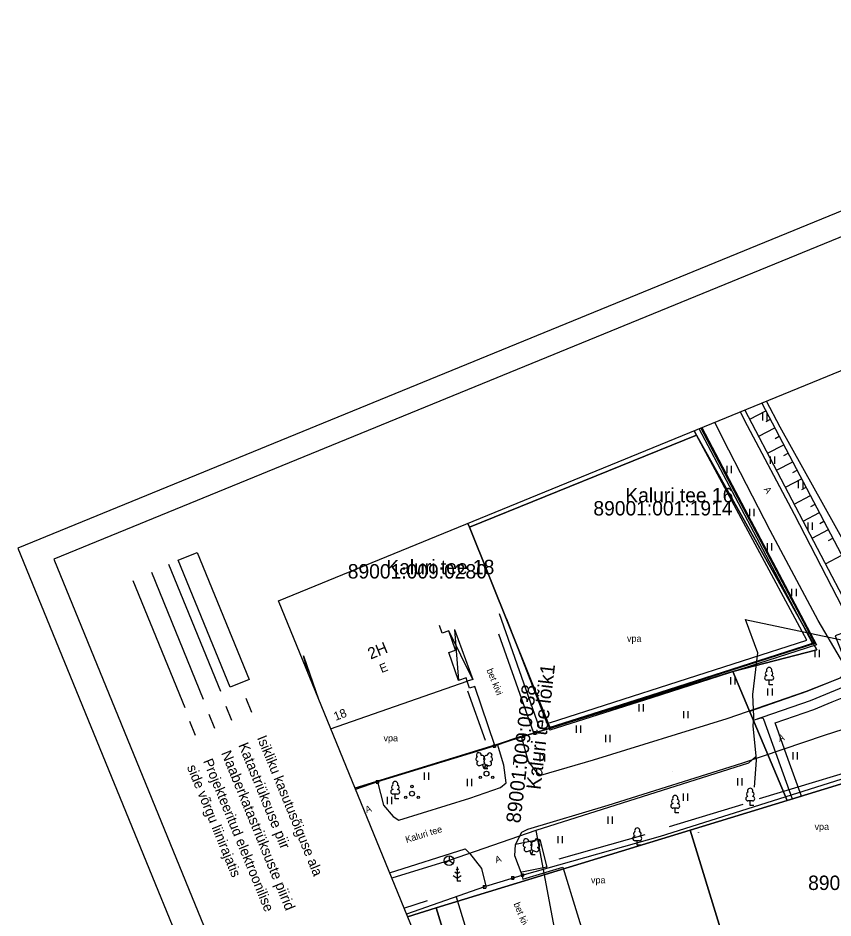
# Model space of a CAD drawing. Extents: x -52238384 to 549205, y 6582846 to 57187752.
# Drawn here: x 546435.6 to 546520.5, y 6597179.7 to 6597273.4 of the extents above; entities that cross this region are included whole.
import ezdxf

# ---------------------------------------------------------------- set-up
doc = ezdxf.new("R2010")
doc.units = 0
for name, color, linetype in [('kaluri tee mõõdistus$0$AED', 7, 'Continuous'), ('kaluri tee mõõdistus$0$HALJASTUS', 7, 'Continuous'), ('kaluri tee mõõdistus$0$HOONE', 7, 'Continuous'), ('kaluri tee mõõdistus$0$HOONEDET', 7, 'Continuous'), ('kaluri tee mõõdistus$0$PUU', 7, 'Continuous'), ('kaluri tee mõõdistus$0$Reljeef', 7, 'Continuous'), ('kaluri tee mõõdistus$0$SIKAEV', 7, 'Continuous'), ('kaluri tee mõõdistus$0$SITRASS', 7, 'Continuous'), ('kaluri tee mõõdistus$0$TEE', 7, 'Continuous'), ('KANAL_ELEMENDID', 7, 'Continuous'), ('KANAL_KAEVUD', 7, 'Continuous'), ('Kasutusala', 7, 'Continuous'), ('L_AADRESS', 7, 'Continuous'), ('Level 52', 7, 'Continuous'), ('Level 63', 7, 'Continuous'), ('PIIR', 7, 'Continuous'), ('TUNNUS', 7, 'Continuous')]:
    doc.layers.add(name, color=color, linetype=linetype)

# ---------------------------------------------------------------- blocks, each defined once
blk = doc.blocks.new('kaluri tee mõõdistus$0$HEIN')
at = {"layer": 'kaluri tee mõõdistus$0$HALJASTUS'}
for p, q in [((-46, 76), (-46, -76)), ((46, 76), (46, -76))]:
    blk.add_line(p, q, dxfattribs=at)
blk = doc.blocks.new('kaluri tee mõõdistus$0$MAND1')
at = {"layer": 'kaluri tee mõõdistus$0$PUU'}
for p, q in [((0, 230), (-25, 247)), ((0, 300), (0, 0)), ((25, 247), (0, 230)), ((-85, 118), (0, 61)), ((0, 150), (-53, 186)), ((53, 186), (0, 150)), ((0, 61), (85, 118)), ((72, 0), (0, 0))]:
    blk.add_line(p, q, dxfattribs=at)
blk = doc.blocks.new('kaluri tee mõõdistus$0$LEHTP1')
at = {"layer": 'kaluri tee mõõdistus$0$PUU'}
for p, q in [((48, 95), (-48, 95)), ((0, 0), (0, 95)), ((76, 0), (0, 0))]:
    blk.add_line(p, q, dxfattribs=at)
for centre, radius, start, end in [((-47, 142), 47.5, 90.0016, 269.3953), ((-34, 235), 46.5, 109.0217, 253.1415), ((0, 304), 55.4, 332.5799, 207.4201), ((34, 235), 46.5, 286.8508, 70.9859), ((47, 142), 47.5, 270.6047, 89.9984)]:
    blk.add_arc(centre, radius, start, end, dxfattribs=at)
blk = doc.blocks.new('kaluri tee mõõdistus$0$LEHTP2')
at = {"layer": 'kaluri tee mõõdistus$0$PUU'}
for p, q in [((-88, 67), (1, 102)), ((0, 0), (-35, 88)), ((0, 0), (36, 88)), ((76, 0), (0, 0)), ((1, 102), (89, 66))]:
    blk.add_line(p, q, dxfattribs=at)
blk.add_lwpolyline([(1, 201), (-3, 186), (-3, 182), (-1, 176), (3, 169), (4, 165), (1, 158), (-4, 148), (-5, 143), (-4, 140), (-2, 134), (5, 122), (6, 118), (5, 114), (2, 107), (1, 102)], dxfattribs=at)
for centre, radius, start, end in [((-126, 201), 44.8, 111.4304, 274.4987), ((-111, 283), 51.2, 111.5027, 232.5173), ((-111, 283), 51.2, 350.4856, 111.5002), ((-44, 233), 44.8, 308.5041, 111.5725), ((1, 153), 47.5, 66.7655, 111.5015), ((48, 232), 45, 67.7016, 230.5126), ((116, 281), 51.2, 67.6168, 188.6314), ((129, 199), 44.8, 264.6183, 67.6866), ((116, 281), 51.2, 306.5997, 67.6143), ((-105, 112), 47.5, 111.5014, 291.5004), ((107, 110), 47.5, 247.6166, 67.6155)]:
    blk.add_arc(centre, radius, start, end, dxfattribs=at)
blk = doc.blocks.new('kaluri tee mõõdistus$0$VARPOS')
at = {"layer": 'kaluri tee mõõdistus$0$AED'}
for p, q in [((-25, 25), (-25, -25)), ((-25, 25), (25, 25)), ((25, 25), (25, -25)), ((-25, -25), (25, -25))]:
    blk.add_line(p, q, dxfattribs=at)
blk = doc.blocks.new('kaluri tee mõõdistus$0$PQQSAS')
at = {"layer": 'kaluri tee mõõdistus$0$PUU'}
for centre, radius in [((0, 0), 50), ((0, 150), 25), ((-130, -75), 25), ((130, -75), 25)]:
    blk.add_circle(centre, radius, dxfattribs=at)
blk = doc.blocks.new('kaluri tee mõõdistus$0$SIKAEV')
at = {"layer": 'kaluri tee mõõdistus$0$SIKAEV'}
for p, q in [((0, 0), (-83, -55)), ((0, 100), (0, 0)), ((0, 0), (83, -55))]:
    blk.add_line(p, q, dxfattribs=at)
blk.add_circle((0, 0), 100, dxfattribs=at)
blk = doc.blocks.new('VKT_kk_olemas_w')
at = {"layer": 'KANAL_ELEMENDID'}
blk.add_line((0, 0), (0, 0), dxfattribs=at)
blk.add_circle((0, 0), 0.1, dxfattribs=at)

msp = doc.modelspace()

# ---------------------------------------------------------------- linework, layer by layer
at = {"layer": 'kaluri tee mõõdistus$0$AED'}
for points in [[(546506.844, 6597230.752), (546509.707, 6597225.356), (546518.818, 6597208.138), (546501.644, 6597202.59), (546491.016, 6597199.217), (546490.926, 6597199.503), (546501.553, 6597202.876), (546517.54, 6597208.004), (546518.391, 6597208.305), (546512.913, 6597218.694), (546506.569, 6597230.64)], [(546506.732, 6597230.706), (546513.987, 6597217.039), (546518.619, 6597208.25), (546491.076, 6597199.407)], [(546490.926, 6597199.503), (546490.866, 6597199.572), (546486.525, 6597210.804)], [(546491.076, 6597199.407), (546489.432, 6597198.954)], [(546488.252, 6597198.617), (546485.218, 6597197.583)], [(546489.432, 6597198.954), (546488.252, 6597198.617)], [(546485.218, 6597197.583), (546473.034, 6597193.848)], [(546488.135, 6597184.138), (546502.555, 6597188.204), (546524.017, 6597194.973)], [(546473.034, 6597193.848), (546470.74, 6597193.068)], [(546489.963, 6597187.858), (546490.701, 6597184.976), (546488.077, 6597184.441)], [(546484.2, 6597182.912), (546476.056, 6597180.077)]]:
    msp.add_lwpolyline(points, dxfattribs=at)
at = {"layer": 'kaluri tee mõõdistus$0$HALJASTUS'}
for p, q in [((546484.29, 6597198.152), (546482.473, 6597203.283)), ((546491.999, 6597185.827), (546500.964, 6597188.363))]:
    msp.add_line(p, q, dxfattribs=at)
for points in [[(546490.976, 6597199.992), (546517.792, 6597208.595), (546506.071, 6597230.436)], [(546489.945, 6597199.476), (546485.749, 6597211.343)], [(546526.412, 6597196.164), (546512.843, 6597192.092)], [(546511.143, 6597191.484), (546503.443, 6597189.176)], [(546489.963, 6597187.858), (546487.425, 6597187.304)], [(546475.807, 6597180.686), (546478.247, 6597181.491)]]:
    msp.add_lwpolyline(points, dxfattribs=at)
at = {"layer": 'kaluri tee mõõdistus$0$HOONE'}
for p, q in [((546481.087, 6597209.717), (546482.969, 6597204.513)), ((546482.969, 6597204.513), (546482.397, 6597204.333))]:
    msp.add_line(p, q, dxfattribs=at)
for points in [[(546468.163, 6597199.366), (546482.397, 6597204.333), (546482.287, 6597204.669), (546481.497, 6597204.394), (546480.479, 6597207.33), (546481.174, 6597207.577), (546480.475, 6597209.588), (546479.789, 6597209.34), (546479.503, 6597210.147)], [(546465.322, 6597206.98), (546466.892, 6597202.471)]]:
    msp.add_lwpolyline(points, dxfattribs=at)
at = {"layer": 'kaluri tee mõõdistus$0$HOONEDET'}
for p, q in [((546482.969, 6597204.513), (546480.475, 6597209.588)), ((546481.087, 6597209.717), (546481.497, 6597204.394)), ((546465.842, 6597205.039), (546465.322, 6597206.98))]:
    msp.add_line(p, q, dxfattribs=at)
at = {"layer": 'kaluri tee mõõdistus$0$Reljeef'}
for p, q in [((546523.368, 6597209.639), (546511.346, 6597232.595)), ((546511.851, 6597231.631), (546513.532, 6597232.515)), ((546513.555, 6597231.397), (546513.997, 6597231.63)), ((546512.779, 6597229.859), (546514.463, 6597230.745)), ((546514.486, 6597229.627), (546514.928, 6597229.86)), ((546513.706, 6597228.087), (546515.394, 6597228.975)), ((546515.417, 6597227.857), (546515.86, 6597228.09)), ((546514.634, 6597226.316), (546516.325, 6597227.205)), ((546516.348, 6597226.087), (546516.791, 6597226.32)), ((546515.562, 6597224.544), (546517.256, 6597225.435)), ((546517.28, 6597224.317), (546517.722, 6597224.55)), ((546516.49, 6597222.772), (546518.188, 6597223.665)), ((546518.211, 6597222.547), (546518.653, 6597222.78)), ((546517.418, 6597221), (546519.119, 6597221.895)), ((546519.142, 6597220.777), (546519.584, 6597221.01)), ((546518.346, 6597219.229), (546520.05, 6597220.125)), ((546520.073, 6597219.007), (546520.516, 6597219.24)), ((546519.738, 6597216.571), (546521.447, 6597217.47))]:
    msp.add_line(p, q, dxfattribs=at)
msp.add_lwpolyline([(546513.11, 6597233.316), (546524.241, 6597212.16), (546523.368, 6597209.639)], dxfattribs=at)
at = {"layer": 'kaluri tee mõõdistus$0$SITRASS'}
msp.add_line((546489.56, 6597188.78), (546493.538, 6597167.649), dxfattribs=at)
for points in [[(546548.663, 6597201.281), (546548.11, 6597201.65), (546545.89, 6597202.29), (546531.554, 6597205.491), (546522.056, 6597208.484), (546511.376, 6597210.741)], [(546512.521, 6597196.519), (546512.193, 6597199.687), (546512.278, 6597200.608), (546512.173, 6597202.942), (546512.689, 6597207.298), (546511.4, 6597210.75)], [(546512.53, 6597196.526), (546511.713, 6597195.812), (546489.56, 6597188.78), (546480.505, 6597185.637)], [(546512.357, 6597193.306), (546512.562, 6597196.115), (546512.52, 6597196.525)], [(546480.505, 6597185.637), (546474.525, 6597183.82)]]:
    msp.add_lwpolyline(points, dxfattribs=at)
at = {"layer": 'kaluri tee mõõdistus$0$TEE'}
for points in [[(546510.834, 6597232.385), (546511.564, 6597230.966), (546516.471, 6597221.744), (546521.48, 6597212.062), (546523.639, 6597208.124), (546524.412, 6597206.815), (546526.775, 6597210.165), (546521.944, 6597218.407), (546515.01, 6597230.79), (546513.582, 6597233.51)], [(546473.034, 6597193.848), (546473.679, 6597191.418), (546474.667, 6597190.222), (546475.266, 6597189.855), (546482.67, 6597192.141), (546485.882, 6597193.259), (546486.464, 6597193.742), (546486.212, 6597195.569), (546485.561, 6597197.791), (546488.008, 6597198.596), (546488.751, 6597195.981), (546489.598, 6597194.886), (546490.075, 6597194.545), (546495.577, 6597196.146), (546509.496, 6597200.439), (546517.764, 6597203.312), (546522.268, 6597205.075), (546521.293, 6597206.702), (546518.984, 6597210.646), (546513.99, 6597220.048), (546509.053, 6597229.628), (546508.194, 6597231.305)], [(546489.313, 6597199.03), (546485.686, 6597209.233)], [(546485.262, 6597197.647), (546483.178, 6597203.793), (546482.63, 6597203.617), (546482.397, 6597204.333)], [(546474.304, 6597184.36), (546482.19, 6597186.874), (546482.631, 6597186.412), (546483.903, 6597184.826), (546484.329, 6597182.997), (546488.135, 6597184.138), (546487.344, 6597186.151), (546487.425, 6597187.304), (546488.091, 6597188.616), (546488.727, 6597188.923), (546497.087, 6597191.418), (546511.02, 6597195.812), (546519.628, 6597198.709), (546523.644, 6597200.01), (546524.855, 6597200.229), (546526.606, 6597200.416)], [(546488.099, 6597184.127), (546488.208, 6597183.721), (546492.368, 6597184.96), (546495.351, 6597175.243), (546491.692, 6597174.115), (546493.192, 6597169.417)], [(546481.24, 6597181.882), (546486.29, 6597165.376)]]:
    msp.add_lwpolyline(points, dxfattribs=at)
at = {"layer": 'Kasutusala'}
msp.add_lwpolyline([(546524.436, 6597204.996), (546523.538, 6597207.384), (546522.64, 6597209.772), (546520.768, 6597209.068), (546521.436, 6597207.292), (546522.103, 6597205.516), (546521.227, 6597204.663), (546519.52, 6597203.964), (546517.813, 6597203.264), (546514.825, 6597202.225), (546511.837, 6597201.185), (546512.915, 6597198.64), (546515.76, 6597191.92), (546517.23, 6597192.37), (546515.859, 6597196.18), (546514.488, 6597199.99), (546516.505, 6597200.691), (546518.522, 6597201.393), (546520.433, 6597202.176), (546522.345, 6597202.96), (546523.39, 6597203.978)], close=True, dxfattribs=at)
at = {"layer": 'Level 52'}
for p, q in [((546451.267, 6597216.528), (546456.68, 6597203.304)), ((546449.478, 6597215.702), (546454.89, 6597202.478)), ((546447.555, 6597214.826), (546452.971, 6597201.604)), ((546459.31, 6597202.579), (546459.905, 6597201.124)), ((546457.237, 6597201.73), (546457.832, 6597200.276)), ((546453.445, 6597200.157), (546454.041, 6597198.702)), ((546455.447, 6597200.904), (546456.043, 6597199.45))]:
    msp.add_line(p, q, dxfattribs=at)
for points in [[(546610.665, 6597175.343), (546570.526, 6597273.43), (546435.57, 6597218.204), (546475.709, 6597120.117)], [(546439.31, 6597217.036), (546477.288, 6597124.229), (546607.423, 6597177.482), (546569.445, 6597270.289)], [(546556.701, 6597251.154), (546585.474, 6597180.84), (546491.483, 6597142.378), (546462.71, 6597212.692)], [(546454.258, 6597217.751), (546459.669, 6597204.527), (546457.687, 6597203.716), (546452.275, 6597216.94)]]:
    msp.add_lwpolyline(points, close=True, dxfattribs=at)
at = {"layer": 'Level 63'}
for points in [[(546512.228, 6597200.262), (546518.168, 6597202.329), (546521.786, 6597203.811), (546523.27, 6597205.256), (546522.056, 6597208.484)], [(546512.228, 6597200.262), (546513.004, 6597200.533), (546513.197, 6597200.509), (546513.279, 6597200.396), (546516.273, 6597192.077)]]:
    msp.add_lwpolyline(points, dxfattribs=at)
at = {"layer": 'PIIR'}
for points in [[(546506.058, 6597230.431), (546506.3, 6597229.96), (546482.62, 6597220.39), (546482.465, 6597220.776)], [(546545.366, 6597164.427), (546544.44, 6597166.05), (546547.7, 6597167.01), (546529.93, 6597196.26), (546515.76, 6597191.92), (546510.07, 6597205.36), (546518.84, 6597207.6), (546506.3, 6597229.96), (546506.058, 6597230.431)], [(546482.465, 6597220.776), (546482.62, 6597220.39), (546491.03, 6597199.44), (546470.693, 6597193.184)], [(546470.693, 6597193.184), (546491.03, 6597199.44), (546510.07, 6597205.36), (546515.76, 6597191.92), (546505.65, 6597188.82), (546479.16, 6597180.71), (546476.173, 6597179.793)], [(546476.173, 6597179.793), (546479.16, 6597180.71), (546488.65, 6597149.72), (546488.497, 6597149.675)]]:
    msp.add_lwpolyline(points, dxfattribs=at)
for points in [[(546491.03, 6597199.44), (546482.62, 6597220.39), (546506.3, 6597229.96), (546518.84, 6597207.6), (546510.07, 6597205.36)], [(546529.93, 6597196.26), (546547.7, 6597167.01), (546544.44, 6597166.05), (546515.25, 6597157.51), (546505.65, 6597188.82), (546515.76, 6597191.92)], [(546479.16, 6597180.71), (546505.65, 6597188.82), (546515.25, 6597157.51), (546488.65, 6597149.72)]]:
    msp.add_lwpolyline(points, close=True, dxfattribs=at)

# ---------------------------------------------------------------- block references
at = {"layer": 'kaluri tee mõõdistus$0$AED', "xscale": 0.005000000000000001, "yscale": 0.005000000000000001, "rotation": -4.073594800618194e-10}
for p in [(546488.252, 6597198.617), (546489.432, 6597198.954), (546485.22, 6597197.585), (546473.034, 6597193.848), (546488.135, 6597184.138), (546487.128, 6597183.849), (546484.2, 6597182.912)]:
    msp.add_blockref('kaluri tee mõõdistus$0$VARPOS', p, dxfattribs=at)
at = {"layer": 'kaluri tee mõõdistus$0$HALJASTUS', "xscale": 0.005000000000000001, "yscale": 0.005000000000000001, "rotation": -4.073594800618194e-10}
for p in [(546513.412, 6597231.863), (546514.214, 6597227.358), (546509.674, 6597226.379), (546517.141, 6597224.836), (546512.055, 6597221.901), (546518.12, 6597220.481), (546513.888, 6597218.321), (546516.445, 6597213.578), (546518.861, 6597207.231), (546510.062, 6597204.374), (546513.941, 6597203.21), (546500.505, 6597201.553), (546505.16, 6597200.848), (546493.982, 6597199.331), (546497.05, 6597198.379), (546490.214, 6597196.35), (546516.568, 6597196.554), (546478.13, 6597194.43), (546482.609, 6597193.795), (546510.785, 6597193.839), (546505.143, 6597192.252), (546474.287, 6597191.92), (546497.289, 6597189.853), (546492.077, 6597187.826)]:
    msp.add_blockref('kaluri tee mõõdistus$0$HEIN', p, dxfattribs=at)
at = {"layer": 'kaluri tee mõõdistus$0$PUU', "xscale": 0.005000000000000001, "yscale": 0.005000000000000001, "rotation": -4.073594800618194e-10}
for name, p in [('kaluri tee mõõdistus$0$LEHTP1', (546513.869, 6597203.969)), ('kaluri tee mõõdistus$0$LEHTP2', (546484.159, 6597195.212)), ('kaluri tee mõõdistus$0$PQQSAS', (546484.403, 6597194.701)), ('kaluri tee mõõdistus$0$LEHTP1', (546474.898, 6597192.095)), ('kaluri tee mõõdistus$0$PQQSAS', (546476.639, 6597192.615)), ('kaluri tee mõõdistus$0$LEHTP1', (546511.897, 6597191.382)), ('kaluri tee mõõdistus$0$LEHTP1', (546504.085, 6597190.629)), ('kaluri tee mõõdistus$0$LEHTP1', (546500.125, 6597187.245)), ('kaluri tee mõõdistus$0$LEHTP2', (546489.088, 6597186.253)), ('kaluri tee mõõdistus$0$MAND1', (546481.358, 6597183.502))]:
    msp.add_blockref(name, p, dxfattribs=at)
at = {"layer": 'kaluri tee mõõdistus$0$SIKAEV', "xscale": 0.005000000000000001, "yscale": 0.005000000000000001, "rotation": -4.073594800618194e-10}
msp.add_blockref('kaluri tee mõõdistus$0$SIKAEV', (546480.505, 6597185.637), dxfattribs=at)
at = {"layer": 'KANAL_KAEVUD', "xscale": 0.010000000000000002, "yscale": 0.010000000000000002, "rotation": -4.073594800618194e-10}
for p in [(546503.752, 6597194.885), (546506.492, 6597188.588), (546463.287, 6597183.299)]:
    msp.add_blockref('VKT_kk_olemas_w', p, dxfattribs=at)

# ---------------------------------------------------------------- texts
at = {"layer": 'kaluri tee mõõdistus$0$HALJASTUS'}
for p in [(546499.052, 6597208.435), (546473.675, 6597198.064), (546518.606, 6597188.835), (546495.296, 6597183.273)]:
    msp.add_text('vpa', height=0.7, rotation=360, dxfattribs=at).set_placement(p)
at = {"layer": 'kaluri tee mõõdistus$0$HOONE'}
for s, height, rotation, p in [('2H', 1.2, 22.1906, (546472.322, 6597206.58)), ('E', 0.9, 22.227, (546473.478, 6597205.177)), ('18', 0.9, 21.21942, (546468.683, 6597200.196))]:
    msp.add_text(s, height=height, rotation=rotation, dxfattribs=at).set_placement(p)
at = {"layer": 'kaluri tee mõõdistus$0$TEE'}
for s, rotation, p in [('A', 302.60033, (546513.28, 6597224.32)), ('bet kivi', 291.84278, (546484.402, 6597205.498)), ('A', 18.66059, (546514.945, 6597198.01)), ('A', 18.66059, (546487.175, 6597195.612)), ('A', 18.66059, (546471.902, 6597190.581)), ('Kaluri tee', 17.05661, (546476.073, 6597187.476)), ('A', 18.66059, (546485.429, 6597185.368)), ('bet kivi', 291.84278, (546487.219, 6597181.143))]:
    msp.add_text(s, height=0.7, rotation=rotation, dxfattribs=at).set_placement(p)
at = {"layer": 'L_AADRESS'}
for s, rotation, p in [('Kaluri tee 16', 360, (546498.879, 6597222.965)), ('Kaluri tee 18', 360, (546473.965, 6597215.479)), ('Kaluri tee lõik1', 83.33546, (546490.036, 6597192.977))]:
    msp.add_text(s, height=1.5, rotation=rotation, dxfattribs=at).set_placement(p)
at = {"layer": 'Level 52'}
for s, height, p in [('Isikliku kasutusõiguse ala', 1.04006, (546460.469, 6597198.434)), ('Katastriüksuse piir', 1.08167, (546458.52, 6597197.678)), ('Naaberkatastriüksuste piirid', 1.08167, (546456.73, 6597196.852)), ('side võrgu liinirajatis', 1.04006, (546453.158, 6597195.39)), ('Projekteeritud elektroonilise', 1.04006, (546454.851, 6597196.014))]:
    msp.add_text(s, height=height, rotation=292.27796, dxfattribs=at).set_placement(p)
at = {"layer": 'TUNNUS'}
for s, rotation, p in [('89001:001:1914', 360, (546495.549, 6597221.601)), ('89001:009:0280', 360, (546469.946, 6597215.034)), ('89001:009:0038', 83.33546, (546487.932, 6597189.491)), ('89001:010:1970', 360, (546517.935, 6597182.58))]:
    msp.add_text(s, height=1.5, rotation=rotation, dxfattribs=at).set_placement(p)

doc.saveas('drawing.dxf')
